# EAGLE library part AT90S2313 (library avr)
MICROCONTROLLER 2 Kbytes FLASH 128 bytes SRAM 128 bytes EEPROM UART
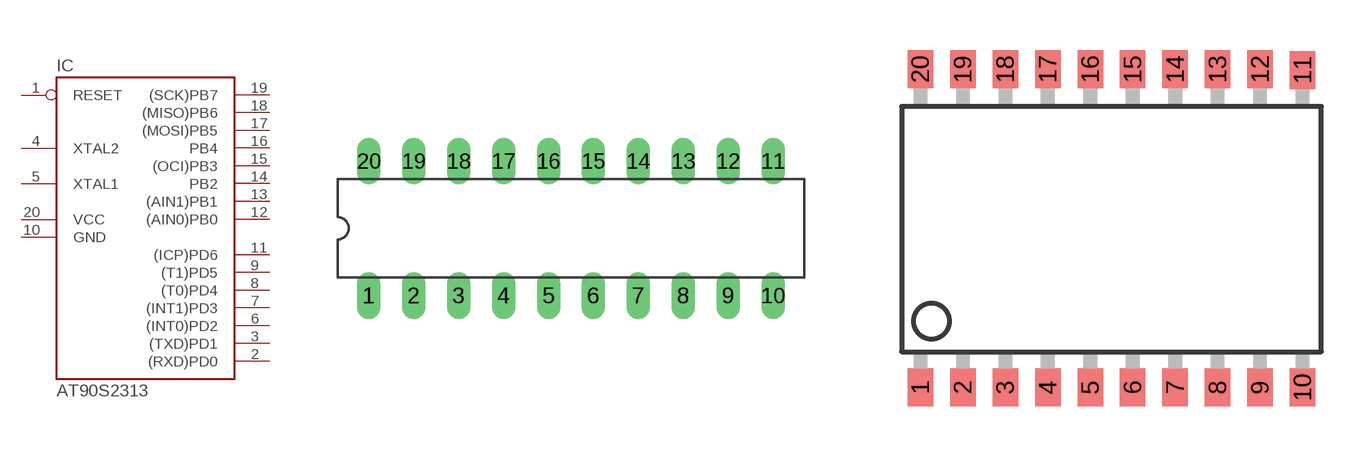
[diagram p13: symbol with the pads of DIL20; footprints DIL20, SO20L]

Designator prefix IC

## AT90S2313P  [DIL20]
1  RESET
2  (RXD)PD0
3  (TXD)PD1
4  XTAL2
5  XTAL1
6  (INT0)PD2
7  (INT1)PD3
8  (T0)PD4
9  (T1)PD5
10  GND  pwr
11  (ICP)PD6
12  (AIN0)PB0
13  (AIN1)PB1
14  PB2
15  (OCI)PB3
16  PB4
17  (MOSI)PB5
18  (MISO)PB6
19  (SCK)PB7
20  VCC  pwr

## AT90S2313S  [SO20L]
Pads as for DIL20

## Footprint DIL20 (pad centres in mm)
Dual In Line
drill 0.813 long: 1 -11.43,-3.81; 2 -8.89,-3.81; 3 -6.35,-3.81; 4 -3.81,-3.81; 5 -1.27,-3.81; 6 1.27,-3.81; 7 3.81,-3.81; 8 6.35,-3.81; 9 8.89,-3.81; 10 11.43,-3.81; 11 11.43,3.81; 12 8.89,3.81; 13 6.35,3.81; 14 3.81,3.81; 15 1.27,3.81; 16 -1.27,3.81; 17 -3.81,3.81; 18 -6.35,3.81; 19 -8.89,3.81; 20 -11.43,3.81

## Footprint SO20L (pad centres in mm)
Small Outline Package
smd 0.762 x 1.143: 1 -5.08,-5.131; 2 -3.81,-5.131; 3 -2.54,-5.131; 4 -1.27,-5.131; 5 0,-5.131; 6 1.27,-5.131; 7 2.54,-5.131; 8 3.81,-5.131; 9 5.08,-5.131; 10 6.35,-5.131; 11 6.35,4.369; 12 5.08,4.394; 13 3.81,4.394; 14 2.54,4.394; 15 1.27,4.394; 16 0,4.394; 17 -1.27,4.394; 18 -2.54,4.394; 19 -3.81,4.394; 20 -5.08,4.394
